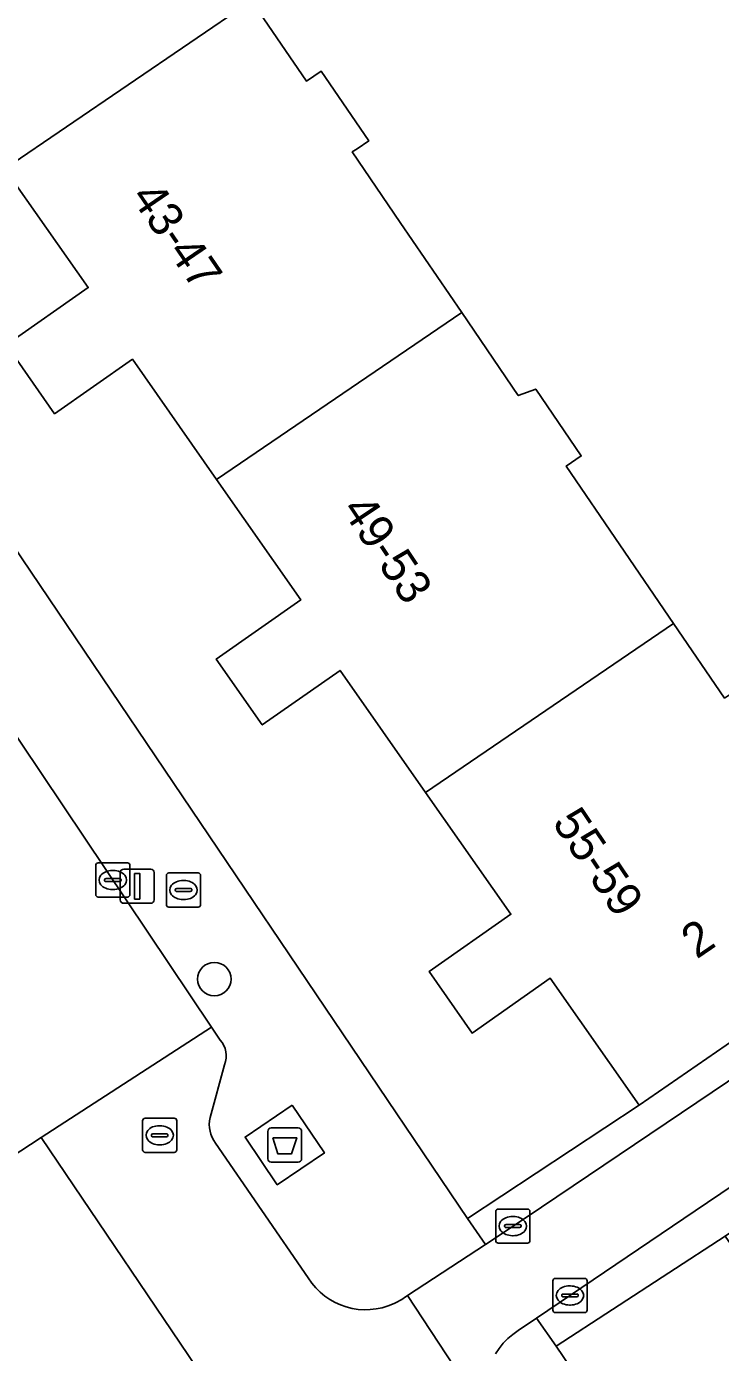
# Model space of a CAD drawing. Extents: x 159888 to 160761, y 384031 to 384750.
# Drawn here: x 160417.48 to 160437.78, y 384295.49 to 384334.29 of the extents above; entities that cross this region are included whole.
import ezdxf

# ---------------------------------------------------------------- set-up
doc = ezdxf.new("R2010")
doc.units = 0
for name, color, linetype in [('IMGEO_Afval_apart_plaats', 7, 'Continuous'), ('IMGEO_Boom', 7, 'Continuous'), ('IMGEO_Brandkraan', 7, 'Continuous'), ('IMGEO_Erf', 7, 'Continuous'), ('IMGEO_Kolk', 7, 'Continuous'), ('IMGEO_Lichtmast', 7, 'Continuous'), ('IMGEO_Pand', 7, 'Continuous'), ('IMGEO_Pand_nummerreeks', 7, 'Continuous'), ('IMGEO_Rijbaan_lokaal_open', 7, 'Continuous'), ('IMGEO_Rioolput', 7, 'Continuous'), ('IMGEO_Voetpad_gesloten', 7, 'Continuous'), ('IMGEO_Voetpad_open', 7, 'Continuous')]:
    doc.layers.add(name, color=color, linetype=linetype)

msp = doc.modelspace()

# ---------------------------------------------------------------- linework, layer by layer
at = {"layer": 'IMGEO_Afval_apart_plaats'}
for p, q in [((160424.538, 384301.158), (160424.538, 384301.958)), ((160424.538, 384301.958), (160424.538, 384301.158)), ((160424.638, 384302.058), (160425.428, 384302.058)), ((160425.428, 384302.058), (160424.638, 384302.058)), ((160425.528, 384301.958), (160425.528, 384301.158)), ((160425.528, 384301.158), (160425.528, 384301.958)), ((160425.428, 384301.058), (160424.638, 384301.058)), ((160424.638, 384301.058), (160425.428, 384301.058))]:
    msp.add_line(p, q, dxfattribs=at)
msp.add_lwpolyline([(160424.681, 384301.772), (160425.385, 384301.772), (160425.236, 384301.302), (160424.83, 384301.302), (160424.681, 384301.772)], dxfattribs=at)
for centre, start, end in [((160424.638, 384301.958), 90, 180), ((160424.638, 384301.958), 90, 180), ((160425.428, 384301.958), 0, 90), ((160425.428, 384301.958), 360, 90), ((160424.638, 384301.158), 180, 270), ((160424.638, 384301.158), 180, 270), ((160425.428, 384301.158), 270, 0), ((160425.428, 384301.158), 270, 0)]:
    msp.add_arc(centre, 0.1, start, end, dxfattribs=at)
at = {"layer": 'IMGEO_Boom'}
msp.add_circle((160422.974, 384306.414), 0.489, dxfattribs=at)
at = {"layer": 'IMGEO_Brandkraan'}
for p, q in [((160421.572, 384308.594), (160421.572, 384309.446)), ((160421.647, 384309.52), (160422.499, 384309.52)), ((160422.573, 384309.446), (160422.573, 384308.594)), ((160421.831, 384309.014), (160421.831, 384309.026)), ((160422.269, 384308.977), (160421.871, 384308.977)), ((160421.874, 384309.063), (160422.272, 384309.063)), ((160422.06, 384309.3), (160422.085, 384309.3)), ((160422.315, 384309.026), (160422.315, 384309.014)), ((160422.083, 384308.74), (160422.058, 384308.74)), ((160422.499, 384308.52), (160421.647, 384308.52))]:
    msp.add_line(p, q, dxfattribs=at)
for points in [[(160421.572, 384308.594), (160421.572, 384309.446)], [(160421.647, 384309.52), (160422.499, 384309.52)], [(160422.573, 384309.446), (160422.573, 384308.594)], [(160422.499, 384308.52), (160421.647, 384308.52)]]:
    msp.add_lwpolyline(points, dxfattribs=at)
for centre, radius, start, end in [((160421.649, 384309.444), 0.0765, 91.552, 178.448), ((160421.649, 384309.444), 0.0765, 91.552, 178.448), ((160422.497, 384309.444), 0.0765, 1.552, 88.448), ((160422.497, 384309.444), 0.0765, 1.552, 88.448), ((160421.871, 384309.023), 0.0403, 85.8775, 175.7526), ((160421.868, 384309.013), 0.0366, 178.938, 274.7102), ((160422.272, 384309.02), 0.043, 264.8664, 352.4533), ((160422.276, 384309.025), 0.0386, 1.7309, 96.639), ((160421.649, 384308.596), 0.0765, 181.552, 268.448), ((160421.649, 384308.596), 0.0765, 181.552, 268.448), ((160422.497, 384308.596), 0.0765, 271.552, 358.448), ((160422.497, 384308.596), 0.0765, 271.552, 358.448)]:
    msp.add_arc(centre, radius, start, end, dxfattribs=at)
for centre, major_axis, ratio, start_param, end_param in [((160422.059, 384309.02), (-0.387, 0.002), 0.722429, 4.712389, 7.853982), ((160422.084, 384309.02), (-0.39, 0.002), 0.717154, 1.570796, 4.712389)]:
    msp.add_ellipse(centre, major_axis=major_axis, ratio=ratio, start_param=start_param, end_param=end_param, dxfattribs=at)
at = {"layer": 'IMGEO_Erf'}
for points in [[(160424.065, 384335.047), (160425.666, 384332.697), (160426.096, 384332.99), (160427.49, 384330.945), (160427.148, 384330.715), (160427.008, 384330.622), (160428.415, 384328.556), (160430.211, 384325.919), (160431.865, 384323.492), (160432.376, 384323.681), (160433.707, 384321.726), (160433.271, 384321.429), (160436.409, 384316.824), (160437.899, 384314.639)], [(160406.906, 384334.176), (160430.378, 384299.406), (160435.399, 384302.726), (160432.802, 384306.438), (160430.513, 384304.836), (160429.254, 384306.635), (160431.649, 384308.311), (160429.151, 384311.879), (160426.654, 384315.447), (160424.377, 384313.853), (160423.028, 384315.781), (160425.504, 384317.514), (160423.041, 384321.035), (160420.578, 384324.555), (160418.299, 384322.96), (160416.889, 384324.975), (160419.284, 384326.651), (160416.848, 384330.131)], [(160440.346, 384295.421), (160437.919, 384298.895), (160432.977, 384295.669), (160463.867, 384250)]]:
    msp.add_lwpolyline(points, dxfattribs=at)
at = {"layer": 'IMGEO_Kolk'}
for p, q in [((160419.503, 384308.889), (160419.503, 384309.741)), ((160419.578, 384309.815), (160420.43, 384309.815)), ((160420.504, 384309.741), (160420.504, 384308.889)), ((160419.762, 384309.309), (160419.762, 384309.321)), ((160419.805, 384309.358), (160420.203, 384309.358)), ((160419.991, 384309.595), (160420.016, 384309.595)), ((160420.246, 384309.321), (160420.246, 384309.309)), ((160420.2, 384309.272), (160419.802, 384309.272)), ((160420.014, 384309.035), (160419.989, 384309.035)), ((160420.43, 384308.815), (160419.578, 384308.815)), ((160431.282, 384299.685), (160432.134, 384299.685)), ((160431.207, 384298.759), (160431.207, 384299.611)), ((160431.509, 384299.228), (160431.907, 384299.228)), ((160431.695, 384299.465), (160431.72, 384299.465)), ((160432.208, 384299.611), (160432.208, 384298.759)), ((160431.466, 384299.179), (160431.466, 384299.191)), ((160431.904, 384299.142), (160431.506, 384299.142)), ((160431.718, 384298.905), (160431.693, 384298.905)), ((160431.95, 384299.191), (160431.95, 384299.179)), ((160432.134, 384298.685), (160431.282, 384298.685)), ((160432.878, 384296.729), (160432.878, 384297.581)), ((160432.953, 384297.655), (160433.805, 384297.655)), ((160433.366, 384297.435), (160433.391, 384297.435)), ((160433.879, 384297.581), (160433.879, 384296.729)), ((160433.137, 384297.149), (160433.137, 384297.161)), ((160433.575, 384297.112), (160433.177, 384297.112)), ((160433.18, 384297.198), (160433.578, 384297.198)), ((160433.621, 384297.161), (160433.621, 384297.149)), ((160433.805, 384296.655), (160432.953, 384296.655)), ((160433.389, 384296.875), (160433.364, 384296.875))]:
    msp.add_line(p, q, dxfattribs=at)
for points in [[(160419.503, 384308.889), (160419.503, 384309.741)], [(160419.578, 384309.815), (160420.43, 384309.815)], [(160420.504, 384309.741), (160420.504, 384308.889)], [(160420.43, 384308.815), (160419.578, 384308.815)], [(160431.282, 384299.685), (160432.134, 384299.685)], [(160431.207, 384298.759), (160431.207, 384299.611)], [(160432.208, 384299.611), (160432.208, 384298.759)], [(160432.134, 384298.685), (160431.282, 384298.685)], [(160432.878, 384296.729), (160432.878, 384297.581)], [(160432.953, 384297.655), (160433.805, 384297.655)], [(160433.879, 384297.581), (160433.879, 384296.729)], [(160433.805, 384296.655), (160432.953, 384296.655)]]:
    msp.add_lwpolyline(points, dxfattribs=at)
for centre, radius, start, end in [((160419.58, 384309.739), 0.0765, 91.552, 178.448), ((160419.58, 384309.739), 0.0765, 91.552, 178.448), ((160420.428, 384309.739), 0.0765, 1.552, 88.448), ((160420.428, 384309.739), 0.0765, 1.552, 88.448), ((160419.802, 384309.318), 0.0403, 85.8775, 175.7526), ((160420.207, 384309.32), 0.0386, 1.7309, 96.639), ((160419.799, 384309.308), 0.0366, 178.938, 274.7102), ((160420.203, 384309.315), 0.043, 264.8664, 352.4533), ((160419.58, 384308.891), 0.0765, 181.552, 268.448), ((160419.58, 384308.891), 0.0765, 181.552, 268.448), ((160420.428, 384308.891), 0.0765, 271.552, 358.448), ((160420.428, 384308.891), 0.0765, 271.552, 358.448), ((160431.284, 384299.609), 0.0765, 91.552, 178.448), ((160431.284, 384299.609), 0.0765, 91.552, 178.448), ((160432.132, 384299.609), 0.0765, 1.552, 88.448), ((160432.132, 384299.609), 0.0765, 1.552, 88.448), ((160431.506, 384299.188), 0.0403, 85.8775, 175.7526), ((160431.911, 384299.19), 0.0386, 1.7309, 96.639), ((160431.503, 384299.178), 0.0366, 178.938, 274.7102), ((160431.907, 384299.185), 0.043, 264.8664, 352.4533), ((160431.284, 384298.761), 0.0765, 181.552, 268.448), ((160431.284, 384298.761), 0.0765, 181.552, 268.448), ((160432.132, 384298.761), 0.0765, 271.552, 358.448), ((160432.132, 384298.761), 0.0765, 271.552, 358.448), ((160432.955, 384297.579), 0.0765, 91.552, 178.448), ((160432.955, 384297.579), 0.0765, 91.552, 178.448), ((160433.803, 384297.579), 0.0765, 1.552, 88.448), ((160433.803, 384297.579), 0.0765, 1.552, 88.448), ((160433.177, 384297.158), 0.0403, 85.8775, 175.7526), ((160433.174, 384297.148), 0.0366, 178.938, 274.7102), ((160433.578, 384297.155), 0.043, 264.8664, 352.4533), ((160433.582, 384297.16), 0.0386, 1.7309, 96.639), ((160432.955, 384296.731), 0.0765, 181.552, 268.448), ((160432.955, 384296.731), 0.0765, 181.552, 268.448), ((160433.803, 384296.731), 0.0765, 271.552, 358.448), ((160433.803, 384296.731), 0.0765, 271.552, 358.448)]:
    msp.add_arc(centre, radius, start, end, dxfattribs=at)
for centre, major_axis, ratio, start_param, end_param in [((160419.99, 384309.315), (-0.387, 0.002), 0.722429, 4.712389, 7.853982), ((160420.015, 384309.315), (-0.39, 0.002), 0.717154, 1.570796, 4.712389), ((160431.694, 384299.185), (-0.387, 0.002), 0.722429, 4.712389, 7.853982), ((160431.719, 384299.185), (-0.39, 0.002), 0.717154, 1.570796, 4.712389), ((160433.365, 384297.155), (-0.387, 0.002), 0.722429, 4.712389, 7.853982), ((160433.39, 384297.155), (-0.39, 0.002), 0.717154, 1.570796, 4.712389)]:
    msp.add_ellipse(centre, major_axis=major_axis, ratio=ratio, start_param=start_param, end_param=end_param, dxfattribs=at)
at = {"layer": 'IMGEO_Lichtmast'}
for p, q in [((160420.223, 384308.732), (160420.223, 384309.532)), ((160420.223, 384309.532), (160420.223, 384308.732)), ((160420.323, 384309.632), (160421.113, 384309.632)), ((160421.113, 384309.632), (160420.323, 384309.632)), ((160421.213, 384309.532), (160421.213, 384308.732)), ((160421.213, 384308.732), (160421.213, 384309.532)), ((160421.113, 384308.632), (160420.323, 384308.632)), ((160420.323, 384308.632), (160421.113, 384308.632))]:
    msp.add_line(p, q, dxfattribs=at)
msp.add_lwpolyline([(160420.643, 384309.507), (160420.793, 384309.507), (160420.793, 384308.757), (160420.643, 384308.757), (160420.643, 384309.507)], dxfattribs=at)
for centre, start, end in [((160420.323, 384309.532), 90, 180), ((160420.323, 384309.532), 90, 180), ((160421.113, 384309.532), 0, 90), ((160421.113, 384309.532), 360, 90), ((160420.323, 384308.732), 180, 270), ((160420.323, 384308.732), 180, 270), ((160421.113, 384308.732), 270, 0), ((160421.113, 384308.732), 270, 0)]:
    msp.add_arc(centre, 0.1, start, end, dxfattribs=at)
at = {"layer": 'IMGEO_Pand'}
for points in [[(160417.858, 384344.151), (160410.686, 384339.264), (160413.186, 384335.692), (160410.75, 384333.987), (160412.132, 384332.013), (160414.413, 384333.61), (160416.848, 384330.131), (160424.065, 384335.047), (160422.25, 384337.711), (160420.864, 384339.742), (160421.35, 384340.074), (160420.01, 384342.04), (160419.523, 384341.708)], [(160424.065, 384335.047), (160416.848, 384330.131), (160419.284, 384326.651), (160416.889, 384324.975), (160418.299, 384322.96), (160420.578, 384324.555), (160423.041, 384321.035), (160430.211, 384325.919), (160428.415, 384328.556), (160427.008, 384330.622), (160427.148, 384330.715), (160427.49, 384330.945), (160426.096, 384332.99), (160425.666, 384332.697)], [(160430.211, 384325.919), (160423.041, 384321.035), (160425.504, 384317.514), (160423.028, 384315.781), (160424.377, 384313.853), (160426.654, 384315.447), (160429.151, 384311.879), (160435.975, 384316.528), (160436.409, 384316.824), (160433.271, 384321.429), (160433.707, 384321.726), (160432.376, 384323.681), (160431.865, 384323.492)], [(160440.677, 384310.562), (160441.08, 384310.832), (160438.308, 384314.912), (160437.899, 384314.639), (160436.409, 384316.824), (160435.975, 384316.528), (160429.151, 384311.879), (160431.649, 384308.311), (160429.254, 384306.635), (160430.513, 384304.836), (160432.802, 384306.438), (160435.399, 384302.726), (160442.188, 384307.409), (160442.622, 384307.708)]]:
    msp.add_lwpolyline(points, close=True, dxfattribs=at)
at = {"layer": 'IMGEO_Rijbaan_lokaal_open'}
for points in [[(160415.801, 384300.405), (160417.91, 384301.776), (160422.888, 384305.012), (160410.478, 384323.524), (160403.531, 384333.459), (160397.147, 384341.932), (160379.601, 384362.826)], [(160482.897, 384333.68), (160474.075, 384327.692), (160468.686, 384324.069), (160462.364, 384319.818), (160461.832, 384319.461), (160453.217, 384313.669), (160449.351, 384311.065), (160432.095, 384299.442), (160430.906, 384298.646), (160428.629, 384297.152), (160431.13, 384293.34)], [(160431.199, 384295.45), (160431.305, 384295.608), (160431.426, 384295.756), (160431.559, 384295.893), (160431.704, 384296.017), (160431.86, 384296.128), (160432.401, 384296.495), (160437.04, 384299.637), (160450.775, 384308.907), (160460.087, 384315.192), (160463.235, 384317.314), (160474.747, 384325.076), (160485.242, 384332.327)], [(160423.141, 384304.631), (160422.888, 384305.012), (160417.91, 384301.776), (160422.932, 384294.34), (160424.309, 384292.356), (160427.008, 384288.421), (160434.682, 384277.153), (160440.091, 384269.157), (160445.772, 384260.903)], [(160422.848, 384302.361), (160423.273, 384303.908)], [(160422.932, 384294.34), (160417.91, 384301.776), (160415.801, 384300.405), (160412.696, 384297.247), (160409.504, 384293.847), (160396.973, 384281.372), (160379.726, 384264.338), (160372.559, 384257.094), (160366.063, 384250.659), (160365.342, 384250), (160363.109, 384247.959), (160360.237, 384245.231), (160359.808, 384244.824), (160358.837, 384243.977), (160356.862, 384242.381), (160355.12, 384241.215), (160350.961, 384238.084), (160345.716, 384234.364), (160345.542, 384234.231)], [(160425.721, 384297.672), (160423.01, 384301.611)], [(160482.459, 384217.19), (160479.496, 384221.749), (160475.984, 384226.996), (160471.895, 384233.016), (160469.592, 384236.438), (160463.845, 384244.806), (160460.293, 384250), (160459.062, 384251.8), (160454.397, 384258.743), (160452.84, 384261.021), (160446.785, 384269.99), (160433.084, 384290.172), (160431.13, 384293.34), (160428.629, 384297.152), (160428.531, 384297.088)]]:
    msp.add_lwpolyline(points, dxfattribs=at)
for centre, radius, start, end in [((160422.638, 384304.166), 0.686, 337.9371, 42.7563), ((160423.755, 384302.164), 0.928, 167.781, 216.5963), ((160427.403, 384298.717), 1.981, 211.8422, 294.73), ((160427.448, 384298.644), 1.896, 294.417, 304.8248)]:
    msp.add_arc(centre, radius, start, end, dxfattribs=at)
at = {"layer": 'IMGEO_Rioolput'}
for p, q in [((160420.95, 384302.344), (160421.802, 384302.344)), ((160420.875, 384301.418), (160420.875, 384302.27)), ((160421.363, 384302.124), (160421.388, 384302.124)), ((160421.876, 384302.27), (160421.876, 384301.418)), ((160421.134, 384301.838), (160421.134, 384301.85)), ((160421.572, 384301.801), (160421.174, 384301.801)), ((160421.177, 384301.887), (160421.575, 384301.887)), ((160421.386, 384301.564), (160421.361, 384301.564)), ((160421.618, 384301.85), (160421.618, 384301.838)), ((160421.802, 384301.344), (160420.95, 384301.344))]:
    msp.add_line(p, q, dxfattribs=at)
for points in [[(160420.95, 384302.344), (160421.802, 384302.344)], [(160420.875, 384301.418), (160420.875, 384302.27)], [(160421.876, 384302.27), (160421.876, 384301.418)], [(160421.802, 384301.344), (160420.95, 384301.344)]]:
    msp.add_lwpolyline(points, dxfattribs=at)
for centre, radius, start, end in [((160420.952, 384302.268), 0.0765, 91.552, 178.448), ((160420.952, 384302.268), 0.0765, 91.552, 178.448), ((160421.8, 384302.268), 0.0765, 1.552, 88.448), ((160421.8, 384302.268), 0.0765, 1.552, 88.448), ((160421.174, 384301.847), 0.0403, 85.8775, 175.7526), ((160421.171, 384301.837), 0.0366, 178.938, 274.7102), ((160421.575, 384301.844), 0.043, 264.8664, 352.4533), ((160421.579, 384301.849), 0.0386, 1.7309, 96.639), ((160420.952, 384301.42), 0.0765, 181.552, 268.448), ((160420.952, 384301.42), 0.0765, 181.552, 268.448), ((160421.8, 384301.42), 0.0765, 271.552, 358.448), ((160421.8, 384301.42), 0.0765, 271.552, 358.448)]:
    msp.add_arc(centre, radius, start, end, dxfattribs=at)
for centre, major_axis, ratio, start_param, end_param in [((160421.362, 384301.844), (-0.387, 0.002), 0.722429, 4.712389, 7.853982), ((160421.387, 384301.844), (-0.39, 0.002), 0.717154, 1.570796, 4.712389)]:
    msp.add_ellipse(centre, major_axis=major_axis, ratio=ratio, start_param=start_param, end_param=end_param, dxfattribs=at)
at = {"layer": 'IMGEO_Voetpad_gesloten'}
msp.add_lwpolyline([(160425.25, 384302.721), (160423.872, 384301.789), (160424.816, 384300.394), (160426.194, 384301.326)], close=True, dxfattribs=at)
at = {"layer": 'IMGEO_Voetpad_open'}
for points in [[(160428.531, 384297.088), (160428.629, 384297.152), (160430.906, 384298.646), (160430.378, 384299.406), (160406.906, 384334.176), (160401.024, 384341.943), (160354.597, 384397.082)], [(160410.478, 384323.524), (160422.888, 384305.012), (160423.141, 384304.631)], [(160423.273, 384303.908), (160422.848, 384302.361)], [(160423.01, 384301.611), (160425.721, 384297.672)], [(160463.867, 384250), (160432.977, 384295.669), (160432.401, 384296.495), (160431.86, 384296.128), (160431.704, 384296.017), (160431.559, 384295.893), (160431.426, 384295.756), (160431.305, 384295.608), (160431.199, 384295.45)]]:
    msp.add_lwpolyline(points, dxfattribs=at)
for points in [[(160449.351, 384311.065), (160449.231, 384312.166), (160442.622, 384307.708), (160442.188, 384307.409), (160435.399, 384302.726), (160430.378, 384299.406), (160430.906, 384298.646), (160432.095, 384299.442)], [(160437.919, 384298.895), (160444.305, 384303.218), (160444.17, 384303.417), (160444.669, 384303.755), (160444.987, 384303.97), (160451.63, 384308.466), (160450.775, 384308.907), (160437.04, 384299.637), (160432.401, 384296.495), (160432.977, 384295.669)], [(160425.25, 384302.721), (160426.194, 384301.326), (160424.816, 384300.394), (160423.872, 384301.789)]]:
    msp.add_lwpolyline(points, close=True, dxfattribs=at)
for centre, radius, start, end in [((160422.638, 384304.166), 0.686, 337.9371, 42.7563), ((160423.755, 384302.164), 0.928, 167.781, 216.5963), ((160427.403, 384298.717), 1.981, 211.8422, 294.73), ((160427.448, 384298.644), 1.896, 294.417, 304.8248)]:
    msp.add_arc(centre, radius, start, end, dxfattribs=at)

# ---------------------------------------------------------------- texts
at = {"layer": 'IMGEO_Pand_nummerreeks'}
for s, rotation, p in [('43-47', 304.3543, (160420.507, 384329.304)), ('49-53', 303.7298, (160426.679, 384320.158)), ('55-59', 304.022, (160432.839, 384310.99)), ('2', 34.3259, (160437.084, 384306.984))]:
    msp.add_text(s, height=1, rotation=rotation, dxfattribs=at).set_placement(p)

doc.saveas('drawing.dxf')
